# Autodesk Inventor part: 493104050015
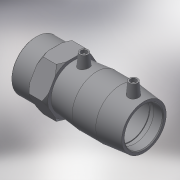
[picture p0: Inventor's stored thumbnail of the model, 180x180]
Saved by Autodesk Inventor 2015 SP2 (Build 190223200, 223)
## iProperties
Created: 2017-06
Part Number: 493104050015
Material: Generic
Description: PLASSON FEMALE TRANSITION COUPLER 50-1.1/2"
Document SubType Name: Modeling
Designer: KIM
Mass: 236.681 g
Surface Area: 517.621 cm^2
Volume: 236.681 cm^3
Density: 1 g/cm^3
Appearance: Default
Author: KIM
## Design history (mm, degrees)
derived "493104.ipt"
feature "Solid1::493104.ipt"
tag "TaggingFeature1"
body "Solid1"
other parameters: "d0" = 101, "d2" = 67, "d3" = 49, "d4" = 33.66667, "d5" = 60.3, "d6" = 47.5, "d8" = 168 deg, "d10" = 19.6, "d11" = 6.53333, "d29" = 51, "d30" = 14, "d31" = 35.35, "d34" = 5 deg, "d41" = 4, "d42" = 14, "d43" = 0, "d48" = 3, "d49" = 0, "d55" = 25, "d57" = 38, "d59" = 44.845, "d60" = 22.5, "d70" = 67, "d71" = 12.5, "d72" = 0, "d73" = 45 deg, "d74" = 3.8, "d75" = 45 deg, "d77" = 0.75, "d80" = 1, "L_" = 126, "L_1" = 49, "D_1" = 67, "A_" = 51, "d_2" = 12, "L_2" = 25, "D_" = 38, "R_p" = 44.845
